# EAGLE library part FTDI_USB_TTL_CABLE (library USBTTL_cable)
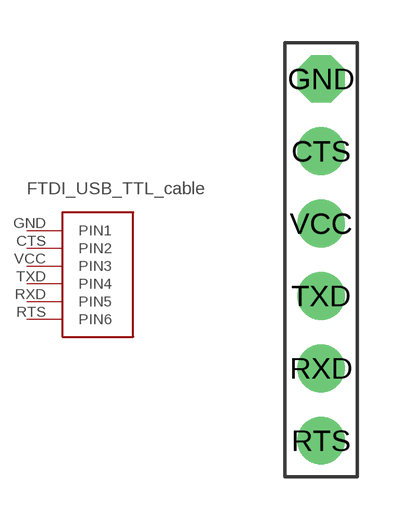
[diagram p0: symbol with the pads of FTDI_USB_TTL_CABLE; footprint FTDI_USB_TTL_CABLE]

Designator prefix -

## FTDI_USB_TTL_CABLE  [FTDI_USB_TTL_CABLE]
CTS  PIN2
GND  PIN1
RTS  PIN6
RXD  PIN5
TXD  PIN4
VCC  PIN3

## Footprint FTDI_USB_TTL_CABLE (pad centres in mm)
drill 0.8 pad 1.676 round: CTS 0,1.27; RTS 0,-8.89; RXD 0,-6.35; TXD 0,-3.81; VCC 0,-1.27
drill 0.8 pad 1.676 octagon: GND 0,3.81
